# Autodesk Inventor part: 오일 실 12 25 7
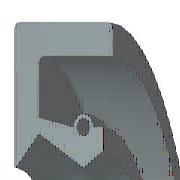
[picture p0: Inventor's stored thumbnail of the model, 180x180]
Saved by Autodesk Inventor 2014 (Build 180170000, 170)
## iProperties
IsCustomPart: 1
Created: 2012-02
Part Number: 오일 실 12 25 7
Material: 고무
Description: 오일-실
Document SubType Name: Modeling
Standard: KS B 2804
Designer: test
Standards Organization: KS
Language: ko-KR
Size Designation: D - 12 25 7
Categories: <MemberInstance><Categories><Category DisplayName="샤프트 부품" InternalName="7f7aeb1f-a693-4053-b835-cee3144e0d98" Mnemonic="SHFT"><Category DisplayName="실링" Intern
Density: 0.93 g/cm^3
Appearance: 고무 - 검은색 - 버전 1.1
Author: test
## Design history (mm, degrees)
revolve "본체" stored, may be unused: angle "d17" = 90 deg
revolve "스프링1" stored, may be unused: angle "d18" = 90 deg
body "Solid1"
sketch "스케치1"
  geometry: L1 (0, 12.5)-(7, 12.5); L2 (7, 10.75)-(1.75, 10.75); L3 (1.75, 7.75)-(4.9, 6); L4 (4.9, 6)-(0, 6); L5 (0, 0)-(9.586, 0) reference; L6 (4.9, 6)-(6.3, 6.875); L7 (0, 18)-(0, -3) reference; L8 (-1.941, 0)-(11.507, 0) reference; L9 (4.2, 8.1)-(1.75, 8.59); L10 (1.75, 8.59)-(1.75, 10.75); L11 (0, 12.5)-(0, 6.088); L12 (4.9, 6)-(0, 6); L13 (1.75, 7.75)-(0.152, 6.028); L14 (7, 12.5)-(7, 10.75); L15 (5.6, 8.1)-(6.3, 8.1); L16 (6.3, 8.1)-(6.3, 6.875); C1 r 0.455 at (4.9, 8.1); A1 r 0.7 centre (4.9, 8.1) between (5.6, 8.1) and (4.2, 8.1); A2 r 0.088 centre (0.088, 6.088) between (0, 6.088) and (0.152, 6.028); 1 further point
  constraints: 28 end point, 5 horizontal alignment, 5 point on line, 4 point on circle, 4 vertical alignment, 3 centre point, 3 tangent, 2 collinear, 2 horizontal, 2 perpendicular, 1 coincident, 1 parallel
  dimensions: "d0" = 25 diameter of L1 L5 (= SD2); "d1" = 1.75 distance of L1.end L2.start (= SD); "d2" = 0.91 diameter of C1 (= SPDI); "d3" = 1.4 diameter of A1 (= SPDA); "d4" = 12 diameter of L3.end L5 (= NND); "d5" = 15.5 diameter of L3.start L5 (= TKDM); "d7" = 17.18 diameter of L9.end L5 (= TKDM + 0.24 x SWDT); "d8" = 1.75 distance between parallel lines of L11 L10 (= SD); "d9" = 4.9 distance from line of L11 C1.centre (= SPDST); "d10" = 16.2 diameter of C1.centre L5 (= HLDM); "d11" = 0.0875 radius of A2 (= 0.25 x LAB); "d12" = 6.3 distance between parallel lines of L11 L16 (= SDI); "d13" = 13.75 diameter of L6.end L5 (= ABDM); "d14" = 7 distance from line of L11 L1.end (= SWDT)
fillet "모깎기1" dims "d6" = 0.3 (= RR)
other parameters: "SD2" = 25 [user parameter; used in 1 equation term], "SWDT" = 7 [user parameter; used in 2 equation terms], "RR" = 0.3 [user parameter; used in 1 equation term], "SD" = 1.75 [user parameter; used in 2 equation terms], "NND" = 12 [user parameter; used in 1 equation term], "SPDA" = 1.4 [user parameter; used in 1 equation term], "SPDI" = 0.91 [user parameter; used in 1 equation term], "TKDM" = 15.5 [user parameter; used in 2 equation terms], "HLDM" = 16.2 [user parameter; used in 1 equation term], "ABDM" = 13.75 [user parameter; used in 1 equation term], "SDI" = 6.3 [user parameter; used in 1 equation term], "SPDST" = 4.9 [user parameter; used in 1 equation term], "LAB" = 0.35 [user parameter; used in 1 equation term], "d15" = 0, "d16" = 0, "d19" = 0
